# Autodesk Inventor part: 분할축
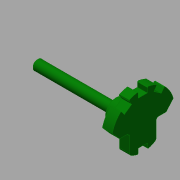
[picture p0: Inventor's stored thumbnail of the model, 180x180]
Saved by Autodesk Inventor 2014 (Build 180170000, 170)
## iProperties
Created: 2016-11
Part Number: 분할축
Material: 강철, 연강
Document SubType Name: Modeling
Designer: mduedu
Density: 1 g/cm^3
Appearance: 진녹색
Author: mduedu
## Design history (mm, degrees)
sketch "스케치1"
  geometry: C1 r 38 at (0, 0); 1 further point
  constraints: 1 centre point, 1 coincident
  dimensions: "d0" = 76 diameter of C1
extrude "돌출1" new body sketch "스케치1" distance "d1" = 12; taper "d2" = 0 deg
sketch "스케치2"
  geometry: L1 (0, 38)-(0, -38); L2 (5.5, 37.6)-(5.5, 31); L3 (5.5, 31)-(-5.5, 31); L4 (-5.5, 31)-(-5.5, 37.6); A1 r 38 centre (0, 0) between (0, 38) and (0, -38) reference; A2 r 38 centre (0, 0) between (5.5, 37.6) and (-5.5, 37.6); 2 further points
  constraints: 8 end point, 6 point on circle, 2 coincident, 2 vertical, 1 centre point, 1 horizontal, 1 midpoint, 1 parallel, 1 symmetric about line
  dimensions: "d3" = 11 distance of L2.end L3.end; "d5" = 31 distance from line of L3 point (0, 0)
extrude "돌출2" cut sketch "스케치2" stored distance "d7" = 12; taper "d8" = 0 deg
sketch "스케치3"
  geometry: L1 (-16, 0)-(-38, 0); L2 (16, 0)-(38, 0); L3 (0, -28)-(0, 28); L4 (-16, -22.978)-(-16, 0); L5 (16, -22.978)-(16, 0); A1 r 38 centre (0, 0) between (-5.5, 37.6) and (-17.061, 33.955) reference; A2 r 38 centre (0, 0) between (-38, 0) and (38, 0); A3 r 28 centre (0, 0) between (-16, -22.978) and (16, -22.978); 4 further points
  constraints: 10 end point, 7 point on circle, 3 coincident, 2 centre point, 2 horizontal alignment, 2 midpoint, 2 parallel, 1 collinear, 1 horizontal, 1 perpendicular, 1 other
  dimensions: "d13" = 32 distance between parallel lines of L5 L4; "d14" = 28 radius of A3
extrude "돌출3" cut sketch "스케치3" stored distance "d15" = 12; taper "d16" = 0 deg
sketch "스케치4"
  geometry: L1 (0, 0)-(0, -28); L2 (5.5, -27.455)-(5.5, -21); L3 (5.5, -21)-(-5.5, -21); L4 (-5.5, -21)-(-5.5, -27.455); A1 r 28 centre (0, 0) between (-16, -22.978) and (16, -22.978) reference; A2 r 28 centre (0, 0) between (16, -22.978) and (0, -28); A3 r 28 centre (0, 0) between (-5.5, -27.455) and (5.5, -27.455); 1 further point
  constraints: 8 end point, 7 point on circle, 2 centre point, 2 coincident, 1 horizontal, 1 parallel, 1 other
  dimensions: "d17" = 11 distance between parallel lines of L2 L4; "d19" = 21 distance from line of L3 point (0, 0)
extrude "돌출4" cut sketch "스케치4" stored distance "d20" = 12; taper "d21" = 0 deg
sketch "스케치5"
  geometry: C1 r 13 at (0, 0); 1 further point
  constraints: 1 centre point, 1 coincident
  dimensions: "d22" = 26 diameter of C1
extrude "돌출5" join sketch "스케치5" distance "d23" = 20; taper "d24" = 0 deg
sketch "스케치6"
  geometry: C1 r 6 at (0, 0); 1 further point
  constraints: 1 centre point, 1 coincident
  dimensions: "d25" = 12 diameter of C1
extrude "돌출6" join sketch "스케치6" distance "d26" = 95; taper "d27" = 0 deg
fillet "모깎기1" dims "d28" = 3
chamfer "모따기1" distance "d29" = 1; stored, may be unused: second distance "d30" = 2, angle "d31" = 45 deg
sketch "스케치7"
  geometry: L1 (-20, 13)-(-20, -13) reference; L2 (-20, 6)-(-114, 6) reference; L3 (0, 0)-(-20, 0); C1 r 1 at (-21, 6)
  constraints: 2 end point, 1 centre point, 1 midpoint, 1 tangent
  dimensions: "d32" = 2 diameter of C1; "d33" = 10 dimension on C1 L3
revolve "회전1" sketch "스케치7" stored, may be unused: angle "d34" = 90 deg
chamfer "모따기2" distance "d35" = 1; stored, may be unused: second distance "d36" = 2, angle "d37" = 45 deg
chamfer "모따기3" distance "d38" = 10; stored, may be unused: second distance "d39" = 2, angle "d40" = 45 deg
chamfer "모따기4" distance "d41" = 1; stored, may be unused: second distance "d42" = 2, angle "d43" = 45 deg
fillet "모깎기2" dims "d44" = 3
node "솔리드1"
pattern_circular "원형 패턴1" dims angle "d10" = 35 deg
other parameters: "d12" = 56
